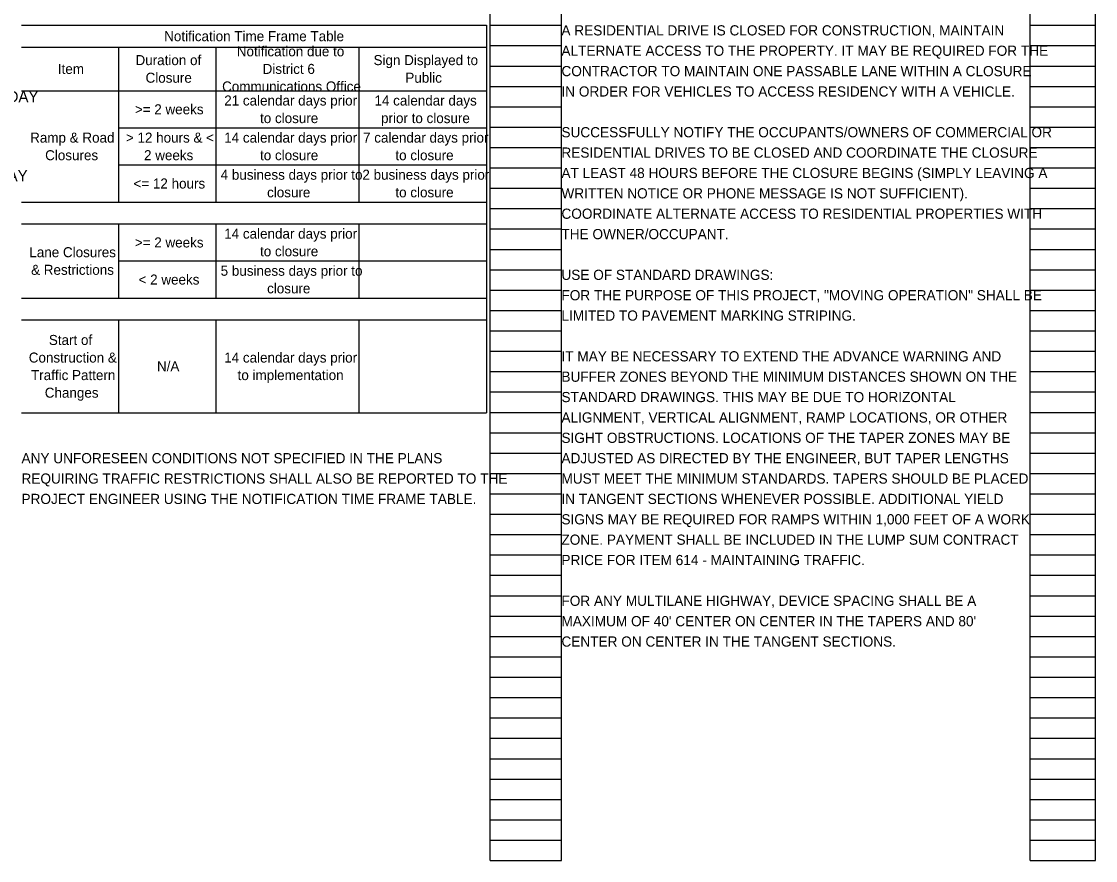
# Model space of a CAD drawing. Extents: x 24172 to 24226.9, y 11011.9 to 11091.2.
# Drawn here: x 24212.19 to 24226.95, y 11071.02 to 11082.55 of the extents above; entities that cross this region are included whole.
import ezdxf

# ---------------------------------------------------------------- set-up
doc = ezdxf.new("R2010")
doc.units = 0
for name, color, linetype in [('Default', 7, 'Continuous'), ('SC_Scratch1', 7, 'Continuous'), ('SH_Data', 7, 'Continuous'), ('SH_Text', 7, 'Continuous')]:
    doc.layers.add(name, color=color, linetype=linetype)

msp = doc.modelspace()

# ---------------------------------------------------------------- linework, layer by layer
at = {"layer": 'SH_Data'}
for p, q in [((24218.63, 11071.019), (24218.63, 11091.179)), ((24219.61, 11071.019), (24219.61, 11091.179)), ((24226.05, 11071.019), (24226.05, 11091.179)), ((24226.95, 11071.019), (24226.95, 11091.179)), ((24218.63, 11082.499), (24219.61, 11082.499)), ((24226.05, 11082.499), (24226.95, 11082.499)), ((24218.63, 11082.219), (24219.61, 11082.219)), ((24226.05, 11082.219), (24226.95, 11082.219)), ((24218.63, 11081.939), (24219.61, 11081.939)), ((24226.05, 11081.939), (24226.95, 11081.939)), ((24218.63, 11081.659), (24219.61, 11081.659)), ((24226.05, 11081.659), (24226.95, 11081.659)), ((24218.63, 11081.379), (24219.61, 11081.379)), ((24226.05, 11081.379), (24226.95, 11081.379)), ((24218.63, 11081.099), (24219.61, 11081.099)), ((24226.05, 11081.099), (24226.95, 11081.099)), ((24218.63, 11080.819), (24219.61, 11080.819)), ((24226.05, 11080.819), (24226.95, 11080.819)), ((24218.63, 11080.539), (24219.61, 11080.539)), ((24226.05, 11080.539), (24226.95, 11080.539)), ((24218.63, 11080.259), (24219.61, 11080.259)), ((24226.05, 11080.259), (24226.95, 11080.259)), ((24218.63, 11079.979), (24219.61, 11079.979)), ((24226.05, 11079.979), (24226.95, 11079.979)), ((24218.63, 11079.699), (24219.61, 11079.699)), ((24226.05, 11079.699), (24226.95, 11079.699)), ((24218.63, 11079.419), (24219.61, 11079.419)), ((24226.05, 11079.419), (24226.95, 11079.419)), ((24218.63, 11079.139), (24219.61, 11079.139)), ((24226.05, 11079.139), (24226.95, 11079.139)), ((24218.63, 11078.859), (24219.61, 11078.859)), ((24226.05, 11078.859), (24226.95, 11078.859)), ((24218.63, 11078.579), (24219.61, 11078.579)), ((24226.05, 11078.579), (24226.95, 11078.579)), ((24218.63, 11078.299), (24219.61, 11078.299)), ((24226.05, 11078.299), (24226.95, 11078.299)), ((24218.63, 11078.019), (24219.61, 11078.019)), ((24226.05, 11078.019), (24226.95, 11078.019)), ((24218.63, 11077.739), (24219.61, 11077.739)), ((24226.05, 11077.739), (24226.95, 11077.739)), ((24218.63, 11077.459), (24219.61, 11077.459)), ((24226.05, 11077.459), (24226.95, 11077.459)), ((24218.63, 11077.179), (24219.61, 11077.179)), ((24226.05, 11077.179), (24226.95, 11077.179)), ((24218.63, 11076.899), (24219.61, 11076.899)), ((24226.05, 11076.899), (24226.95, 11076.899)), ((24218.63, 11076.619), (24219.61, 11076.619)), ((24226.05, 11076.619), (24226.95, 11076.619)), ((24218.63, 11076.339), (24219.61, 11076.339)), ((24226.05, 11076.339), (24226.95, 11076.339)), ((24218.63, 11076.059), (24219.61, 11076.059)), ((24226.05, 11076.059), (24226.95, 11076.059)), ((24218.63, 11075.779), (24219.61, 11075.779)), ((24226.05, 11075.779), (24226.95, 11075.779)), ((24218.63, 11075.499), (24219.61, 11075.499)), ((24226.05, 11075.499), (24226.95, 11075.499)), ((24218.63, 11075.219), (24219.61, 11075.219)), ((24226.05, 11075.219), (24226.95, 11075.219)), ((24218.63, 11074.939), (24219.61, 11074.939)), ((24226.05, 11074.939), (24226.95, 11074.939)), ((24218.63, 11074.659), (24219.61, 11074.659)), ((24226.05, 11074.659), (24226.95, 11074.659)), ((24218.63, 11074.379), (24219.61, 11074.379)), ((24226.05, 11074.379), (24226.95, 11074.379)), ((24218.63, 11074.099), (24219.61, 11074.099)), ((24226.05, 11074.099), (24226.95, 11074.099)), ((24218.63, 11073.819), (24219.61, 11073.819)), ((24226.05, 11073.819), (24226.95, 11073.819)), ((24218.63, 11073.539), (24219.61, 11073.539)), ((24226.05, 11073.539), (24226.95, 11073.539)), ((24218.63, 11073.259), (24219.61, 11073.259)), ((24226.05, 11073.259), (24226.95, 11073.259)), ((24218.63, 11072.979), (24219.61, 11072.979)), ((24226.05, 11072.979), (24226.95, 11072.979)), ((24218.63, 11072.699), (24219.61, 11072.699)), ((24226.05, 11072.699), (24226.95, 11072.699)), ((24218.63, 11072.419), (24219.61, 11072.419)), ((24226.05, 11072.419), (24226.95, 11072.419)), ((24218.63, 11072.139), (24219.61, 11072.139)), ((24226.05, 11072.139), (24226.95, 11072.139)), ((24218.63, 11071.859), (24219.61, 11071.859)), ((24226.05, 11071.859), (24226.95, 11071.859)), ((24218.63, 11071.579), (24219.61, 11071.579)), ((24226.05, 11071.579), (24226.95, 11071.579)), ((24218.63, 11071.299), (24219.61, 11071.299)), ((24226.05, 11071.299), (24226.95, 11071.299)), ((24218.63, 11071.019), (24219.61, 11071.019)), ((24226.05, 11071.019), (24226.95, 11071.019))]:
    msp.add_line(p, q, dxfattribs=at)
at = {"layer": 'SH_Text'}
for p, q in [((24212.19, 11082.499), (24218.58, 11082.499)), ((24218.58, 11082.499), (24218.58, 11077.174)), ((24212.19, 11082.199), (24218.58, 11082.199)), ((24213.525, 11082.199), (24213.525, 11080.069)), ((24214.86, 11082.199), (24214.86, 11080.069)), ((24216.825, 11082.199), (24216.825, 11080.069)), ((24212.19, 11081.599), (24218.58, 11081.599)), ((24213.525, 11081.089), (24218.58, 11081.089)), ((24213.525, 11080.579), (24218.58, 11080.579)), ((24212.19, 11080.069), (24218.58, 11080.069)), ((24212.19, 11079.769), (24218.58, 11079.769)), ((24213.525, 11079.769), (24213.525, 11078.749)), ((24214.86, 11079.769), (24214.86, 11078.749)), ((24216.825, 11079.769), (24216.825, 11078.749)), ((24213.525, 11079.259), (24218.58, 11079.259)), ((24212.19, 11078.749), (24218.58, 11078.749)), ((24212.19, 11078.449), (24218.58, 11078.449)), ((24213.525, 11078.449), (24213.525, 11077.174)), ((24214.86, 11078.449), (24214.86, 11077.174)), ((24216.825, 11078.449), (24216.825, 11077.174)), ((24212.19, 11077.174), (24218.58, 11077.174))]:
    msp.add_line(p, q, dxfattribs=at)

# ---------------------------------------------------------------- texts
at = {"layer": 'Default'}
for s, p in [('A RESIDENTIAL DRIVE IS CLOSED FOR CONSTRUCTION, MAINTAIN ', (24219.61, 11082.359)), ('ALTERNATE ACCESS TO THE PROPERTY. IT MAY BE REQUIRED FOR THE ', (24219.61, 11082.079)), ('CONTRACTOR TO MAINTAIN ONE PASSABLE LANE WITHIN A CLOSURE ', (24219.61, 11081.799)), ('IN ORDER FOR VEHICLES TO ACCESS RESIDENCY WITH A VEHICLE.', (24219.61, 11081.519)), ('SUCCESSFULLY NOTIFY THE OCCUPANTS/OWNERS OF COMMERCIAL OR ', (24219.61, 11080.959)), ('RESIDENTIAL DRIVES TO BE CLOSED AND COORDINATE THE CLOSURE ', (24219.61, 11080.679)), ('AT LEAST 48 HOURS BEFORE THE CLOSURE BEGINS (SIMPLY LEAVING A ', (24219.61, 11080.399)), ('WRITTEN NOTICE OR PHONE MESSAGE IS NOT SUFFICIENT). ', (24219.61, 11080.119)), ('COORDINATE ALTERNATE ACCESS TO RESIDENTIAL PROPERTIES WITH ', (24219.61, 11079.839)), ('THE OWNER/OCCUPANT.', (24219.61, 11079.559))]:
    msp.add_text(s, height=0.14, dxfattribs=at).set_placement(p)
at = {"layer": 'SC_Scratch1'}
for s, p in [('USE OF STANDARD DRAWINGS:', (24219.61, 11078.999)), ('FOR THE PURPOSE OF THIS PROJECT, "MOVING OPERATION" SHALL BE ', (24219.61, 11078.719)), ('LIMITED TO PAVEMENT MARKING STRIPING.', (24219.61, 11078.439)), ('IT MAY BE NECESSARY TO EXTEND THE ADVANCE WARNING AND ', (24219.61, 11077.879)), ('BUFFER ZONES BEYOND THE MINIMUM DISTANCES SHOWN ON THE ', (24219.61, 11077.599)), ('STANDARD DRAWINGS. THIS MAY BE DUE TO HORIZONTAL ', (24219.61, 11077.319)), ('ALIGNMENT, VERTICAL ALIGNMENT, RAMP LOCATIONS, OR OTHER ', (24219.61, 11077.039)), ('SIGHT OBSTRUCTIONS. LOCATIONS OF THE TAPER ZONES MAY BE ', (24219.61, 11076.759)), ('ANY UNFORESEEN CONDITIONS NOT SPECIFIED IN THE PLANS ', (24212.19, 11076.479)), ('ADJUSTED AS DIRECTED BY THE ENGINEER, BUT TAPER LENGTHS ', (24219.61, 11076.479)), ('REQUIRING TRAFFIC RESTRICTIONS SHALL ALSO BE REPORTED TO THE ', (24212.19, 11076.199)), ('MUST MEET THE MINIMUM STANDARDS. TAPERS SHOULD BE PLACED ', (24219.61, 11076.199)), ('PROJECT ENGINEER USING THE NOTIFICATION TIME FRAME TABLE.', (24212.19, 11075.919)), ('IN TANGENT SECTIONS WHENEVER POSSIBLE. ADDITIONAL YIELD ', (24219.61, 11075.919)), ('SIGNS MAY BE REQUIRED FOR RAMPS WITHIN 1,000 FEET OF A WORK ', (24219.61, 11075.639)), ('ZONE. PAYMENT SHALL BE INCLUDED IN THE LUMP SUM CONTRACT ', (24219.61, 11075.359)), ('PRICE FOR ITEM 614 - MAINTAINING TRAFFIC.', (24219.61, 11075.079)), ('FOR ANY MULTILANE HIGHWAY, DEVICE SPACING SHALL BE A ', (24219.61, 11074.519)), ("MAXIMUM OF 40' CENTER ON CENTER IN THE TAPERS AND 80' ", (24219.61, 11074.239)), ('CENTER ON CENTER IN THE TANGENT SECTIONS.', (24219.61, 11073.959))]:
    msp.add_text(s, height=0.14, dxfattribs=at).set_placement(p)
at = {"layer": 'SH_Data'}
for s, p in [('6:00 AM WEDNESDAY THROUGH 6:00 AM MONDAY', (24207.388, 11081.442)), ('12:00 NOON FRIDAY THROUGH 6:00 AM MONDAY', (24207.388, 11080.355))]:
    msp.add_text(s, height=0.154, dxfattribs=at).set_placement(p)
at = {"layer": 'SH_Text'}
for s, p in [('Notification Time Frame Table', (24214.151, 11082.28)), ('Notification due to ', (24215.149, 11082.072)), ('Item', (24212.69, 11081.83)), ('Duration of ', (24213.757, 11081.951)), ('District 6 ', (24215.504, 11081.83)), ('Sign Displayed to ', (24217.028, 11081.951)), ('Closure', (24213.895, 11081.709)), ('Public', (24217.465, 11081.709)), ('Communications Office', (24214.947, 11081.589)), ('21 calendar days prior ', (24214.976, 11081.396)), ('14 calendar days ', (24217.041, 11081.396)), ('>= 2 weeks', (24213.748, 11081.275)), ('to closure', (24215.468, 11081.154)), ('prior to closure', (24217.131, 11081.154)), ('Ramp & Road ', (24212.309, 11080.886)), ('> 12 hours & < ', (24213.625, 11080.886)), ('14 calendar days prior ', (24214.976, 11080.886)), ('7 calendar days prior ', (24216.884, 11080.886)), ('Closures', (24212.515, 11080.644)), ('2 weeks', (24213.874, 11080.644)), ('to closure', (24215.468, 11080.644)), ('to closure', (24217.328, 11080.644)), ('4 business days prior to ', (24214.927, 11080.376)), ('2 business days prior ', (24216.875, 11080.376)), ('<= 12 hours', (24213.729, 11080.255)), ('closure', (24215.565, 11080.134)), ('to closure', (24217.328, 11080.134)), ('14 calendar days prior ', (24214.976, 11079.566)), ('>= 2 weeks', (24213.748, 11079.445)), ('to closure', (24215.468, 11079.324)), ('Lane Closures ', (24212.298, 11079.311)), ('& Restrictions', (24212.322, 11079.069)), ('5 business days prior to ', (24214.927, 11079.056)), ('< 2 weeks', (24213.799, 11078.935)), ('closure', (24215.565, 11078.814)), ('Start of ', (24212.566, 11078.105)), ('Construction & ', (24212.29, 11077.863)), ('14 calendar days prior ', (24214.976, 11077.863)), ('N/A', (24214.052, 11077.743)), ('Traffic Pattern ', (24212.321, 11077.622)), ('to implementation', (24215.16, 11077.622)), ('Changes', (24212.51, 11077.38))]:
    msp.add_text(s, height=0.138, dxfattribs=at).set_placement(p)

doc.saveas('drawing.dxf')
